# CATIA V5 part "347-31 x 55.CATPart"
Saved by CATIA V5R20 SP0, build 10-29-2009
Part number: 347-31 x 55
Definition: NONE
Nomenclature: 347-31 x 55
Source: Unknown
Description: 347-31 x 55
Bounding box of the stored display mesh (mm): x 0 to 55, y -22.5 to 22.5, z -22.5 to 22.5
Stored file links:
  C:\Users\Utente\Desktop\IO LAVORO\3D X SITO CF\X SITO\3D files 347\347-31 x 55.CATPart
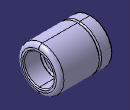
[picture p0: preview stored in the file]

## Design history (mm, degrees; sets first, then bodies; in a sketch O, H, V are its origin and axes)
Body1 "347-31 x 55" (main body)
  Solid1: solid without history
